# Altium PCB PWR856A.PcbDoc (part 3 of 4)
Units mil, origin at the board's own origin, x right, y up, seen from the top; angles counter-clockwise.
Board outline 4000 x 4000 mil, 8 copper layers (Top Layer, Signal Layer 1, Signal Layer 2, Signal Layer 3, Signal Layer 4, Signal Layer 5, Signal Layer 6, Bottom Layer), stack 60.4 mil thick; 246 components, 78 nets, 563 pads, 817 vias.
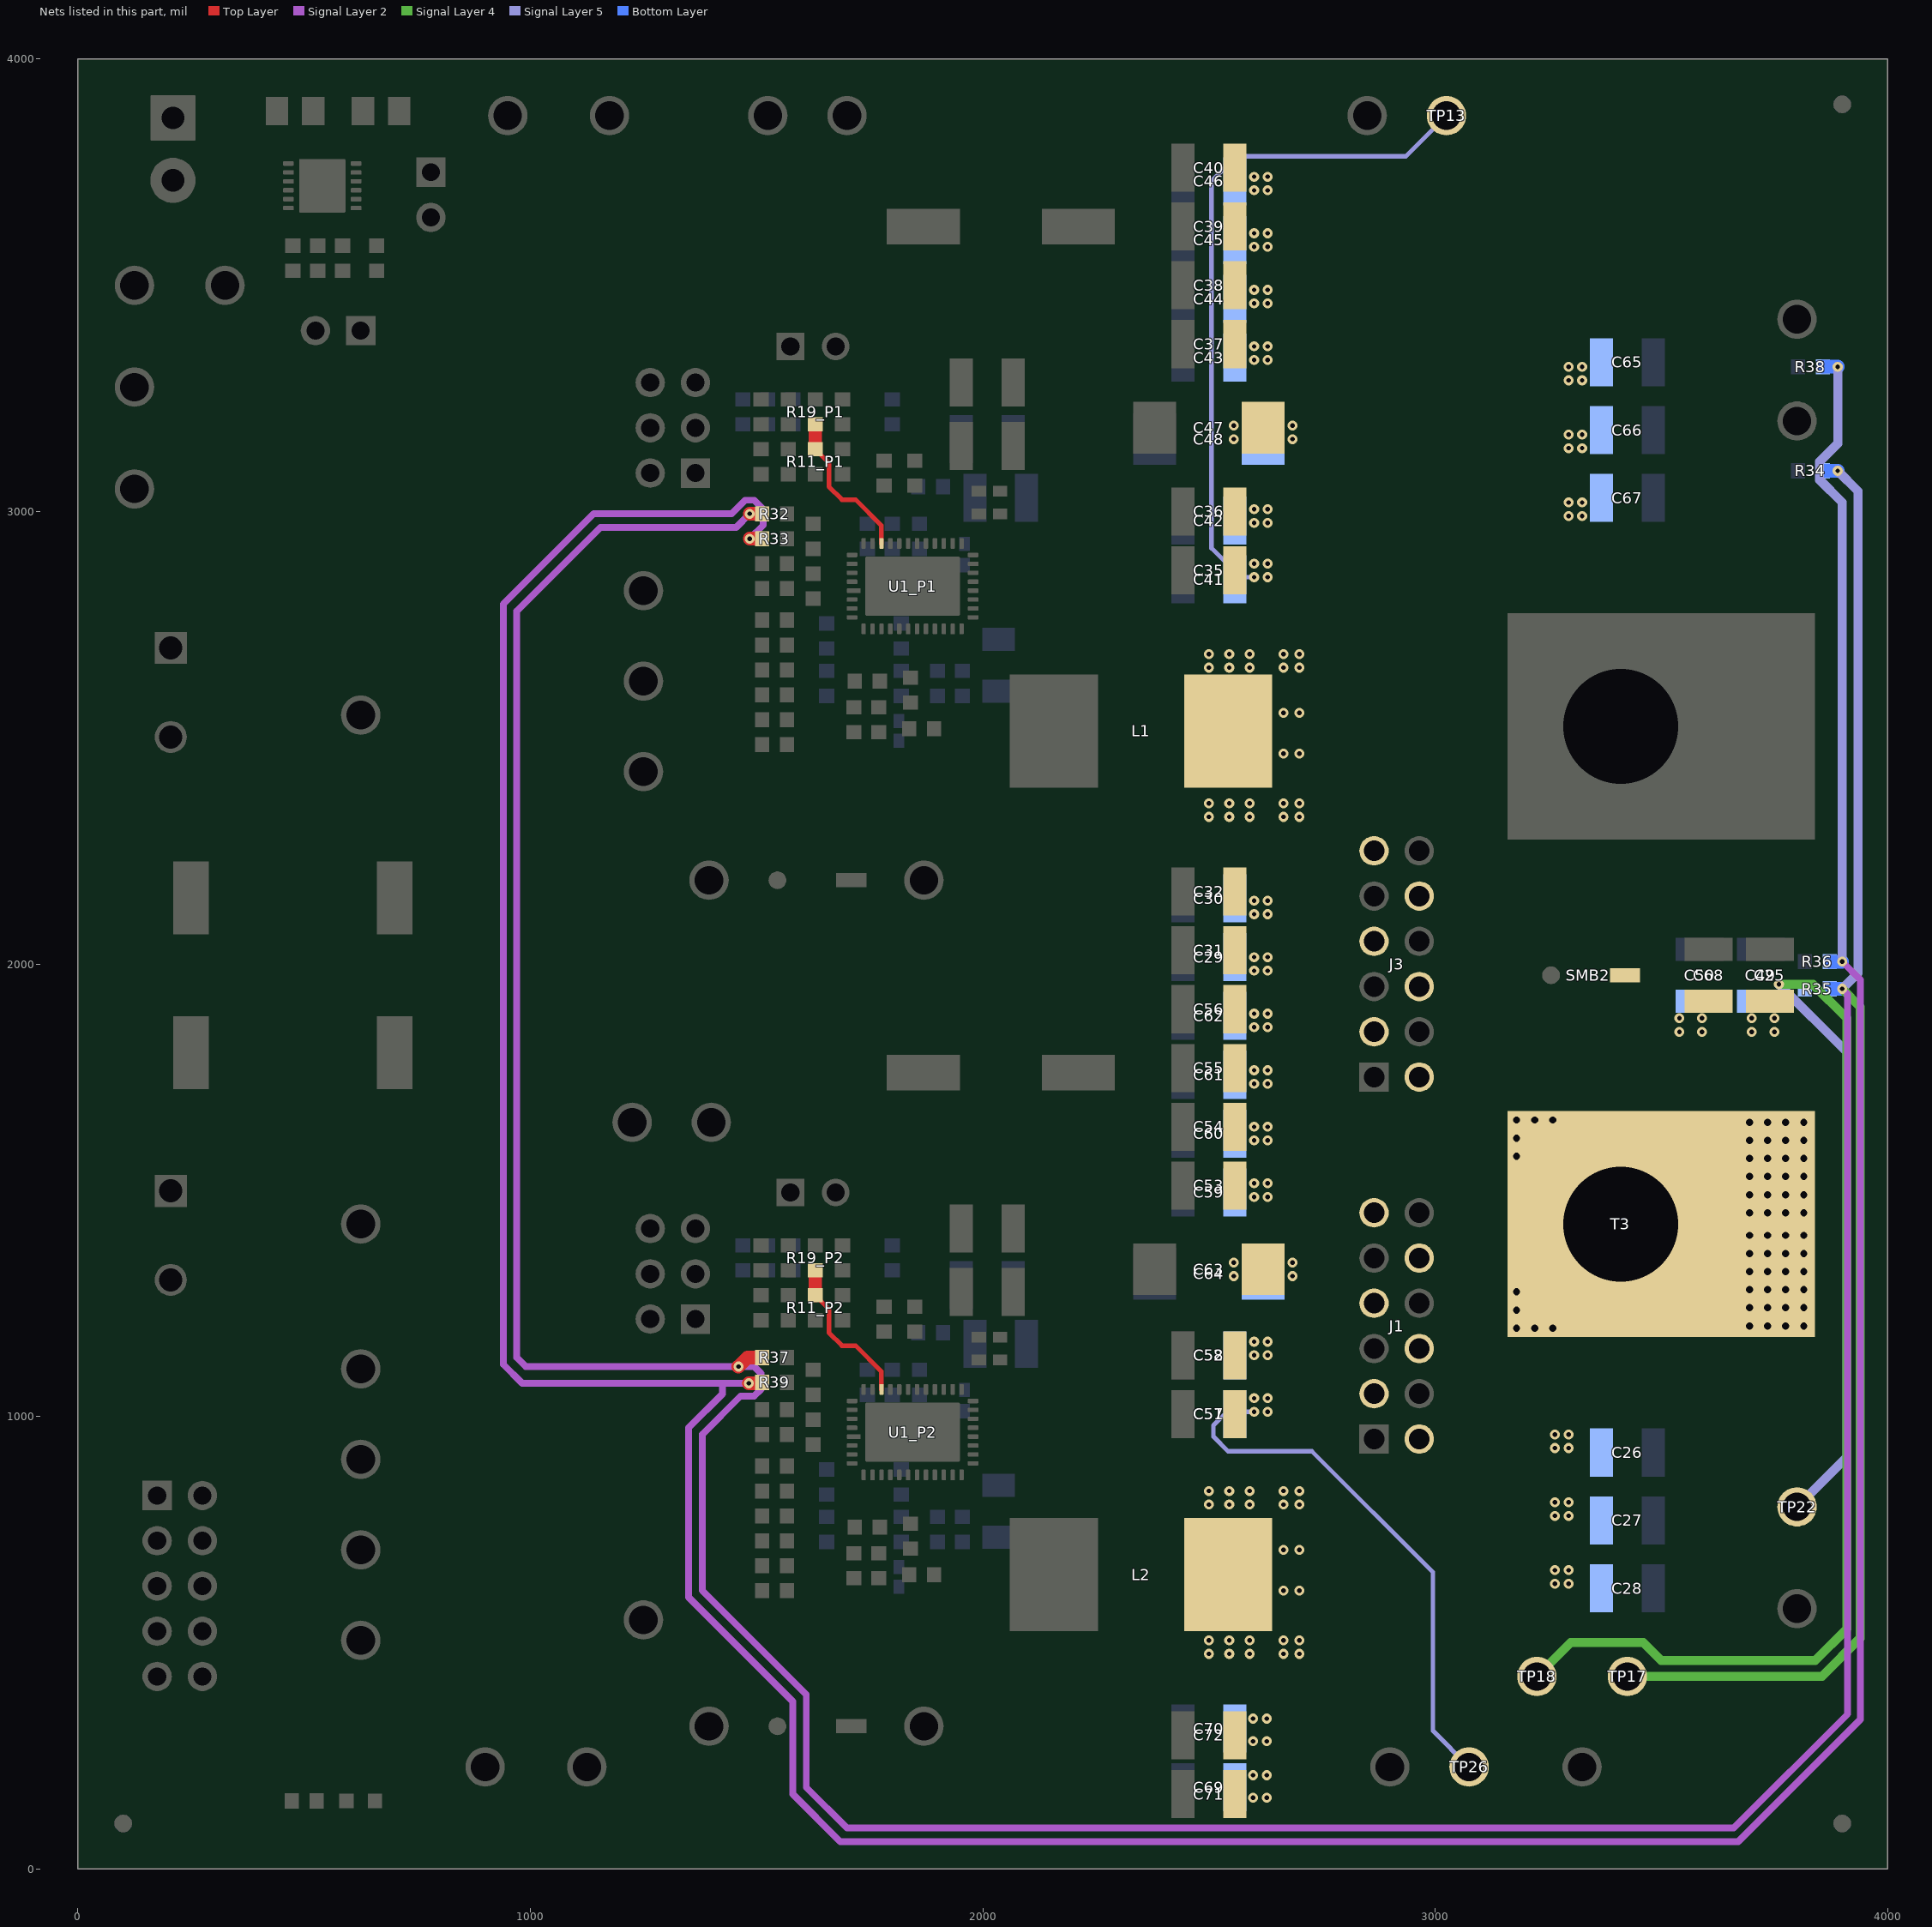
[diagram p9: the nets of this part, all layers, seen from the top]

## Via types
v1: diameter 22, hole 10, Top Layer to Bottom Layer, tented both sides, 676 vias
v2: diameter 32, hole 16, Top Layer to Bottom Layer, 116 vias
v3: diameter 22, hole 10, Top Layer to Bottom Layer, tented bottom, 20 vias
v4: diameter 19.68, hole 7.87, Top Layer to Bottom Layer, 5 vias

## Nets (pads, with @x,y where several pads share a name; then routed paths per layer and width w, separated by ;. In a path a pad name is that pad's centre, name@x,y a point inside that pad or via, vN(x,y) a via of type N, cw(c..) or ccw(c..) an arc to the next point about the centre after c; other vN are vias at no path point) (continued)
VOUT: C25.1 C26.1 C27.1 C28.1 C29.1 C30.1 C31.1 C32.1 C35.2 C36.2 C37.2 C38.2 C39.2 C40.2 C41.2 C42.2 C43.2 C44.2 C45.2 C46.2 C47.1 C48.1 C49.2 C50.2 C51.2 C52.2 C53.2 C54.2 C55.2 C56.2 C57.2 C58.2 C59.2 C60.2 C61.2 C62.2 C63.1 C64.1 C65.1 C66.1 C67.1 C68.1 C69.1 C70.1 C71.1 C72.1 J1.2 J1.3 J1.6 J1.7 J1.10 J1.11 J3.2 J3.3 J3.6 J3.7 J3.10 J3.11 L1.2 L2.2 R35.1 SMB2.1 T3.1 TP13.1 TP18.1 TP22.1 TP26.1 | length 6266.8
  Signal Layer 4 w20: TP18.1@3225,425 3300,500 3460,500 3500,460 3840,460 3910,530 3910,1880 3835,1955 v1(3760,1955)
  Signal Layer 5 w10: v1(2600,1010) 2540,1010 2510,980 2510,955.18 2542.26,922.92 2727.53,922.92 2995,655.46 2995,305 TP26.1@3075,225 ; v1(2600,2855) 2569.61,2855 2505.81,2918.8 2505.81,3730.63 2560.18,3785 2935,3785 TP13.1@3025,3875
  Signal Layer 5 w20: v1(3760,1955) 3910,1805 3910,910 TP22.1@3800,800
  other v1: 2597.81,156.8 2627.81,156.8 2597.81,206.8 2627.81,206.8 2597.81,281.8 2627.81,281.8 2597.81,331.8 2627.81,331.8 2500,475 2545,475 2590,475 2665,475 2700,475 2500,505 2545,505 2590,505 2665,505 2700,505 2665,615 2700,615 3265,630 3295,630 3265,660 3295,660 2665,705 2700,705 3265,780 3295,780 2500,805 2545,805 2590,805 2665,805 2700,805 3265,810 3295,810 2500,835 2545,835 2590,835 2665,835 2700,835 3265,930 3295,930 3265,960 3295,960 2630,1010 2600,1040 2630,1040 2600,1135 2630,1135 2600,1165 2630,1165 2555,1310 2685,1310 2555,1340 2685,1340 2600,1485 2630,1485 2600,1515 2630,1515 2600,1610 2630,1610 2600,1640 2630,1640 2600,1735 2630,1735 2600,1765 2630,1765 3540,1850 3590,1850 3700,1850 3750,1850 2600,1860 2630,1860 3540,1880 3590,1880 3700,1880 3750,1880 2600,1890 2630,1890 2600,1985 2630,1985 2600,2015 2630,2015 2600,2110 2630,2110 2600,2140 2630,2140 2500,2325 2545,2325 2590,2325 2665,2325 2700,2325 2500,2355 2545,2355 2590,2355 2665,2355 2700,2355 2665,2465 2700,2465 2665,2555 2700,2555 2500,2655 2545,2655 2590,2655 2665,2655 2700,2655 2500,2685 2545,2685 2590,2685 2665,2685 2700,2685 2630,2855 2600,2885 2630,2885 2600,2975 2630,2975 3295,2990 3325,2990 2600,3005 2630,3005 3295,3020 3325,3020 3295,3140 3325,3140 2555,3160 2685,3160 3295,3170 3325,3170 2555,3190 2685,3190 3295,3290 3325,3290 3295,3320 3325,3320 2600,3335 2630,3335 2600,3365 2630,3365 2600,3460 2630,3460 2600,3490 2630,3490 2600,3585 2630,3585 2600,3615 2630,3615 2600,3710 2630,3710 2600,3740 2630,3740
  other v2: 3180,1195 3220,1195 3260,1195 3695,1200 3735,1200 3775,1200 3815,1200 3180,1235 3695,1240 3735,1240 3775,1240 3815,1240 3180,1275 3695,1280 3735,1280 3775,1280 3815,1280 3695,1320 3735,1320 3775,1320 3815,1320 3695,1360 3735,1360 3775,1360 3815,1360 3695,1400 3735,1400 3775,1400 3815,1400 3695,1450 3735,1450 3775,1450 3815,1450 3695,1490 3735,1490 3775,1490 3815,1490 3695,1530 3735,1530 3775,1530 3815,1530 3695,1570 3735,1570 3775,1570 3815,1570 3180,1575 3695,1610 3735,1610 3775,1610 3815,1610 3180,1615 3695,1650 3735,1650 3775,1650 3815,1650 3180,1655 3220,1655 3260,1655
VSEL_P1: R11_P1.2 R19_P1.1 U1_P1.30 | length 341
  Top Layer w10: R11_P1.2@1630,3137.56 1660,3107.56 1660,3055 1688.87,3026.13 1718.87,3026.13 1776.1,2968.9 U1_P1.30@1776.1,2929.49
  Top Layer w30: R11_P1.2@1630,3137.56 R19_P1.1@1630,3192.44
VSEL_P2: R11_P2.2 R19_P2.1 U1_P2.30 | length 341
  Top Layer w10: R11_P2.2@1630,1267.56 1660,1237.56 1660,1185 1688.87,1156.13 1718.87,1156.13 1776.1,1098.9 U1_P2.30@1776.1,1059.49
  Top Layer w30: R11_P2.2@1630,1267.56 R19_P2.1@1630,1322.44
VSNS_N: R33.2 R36.2 R38.1 R39.2 | length 9704.4
  Top Layer w30: v1(1482.92,1073) R39.2@1510.36,1073 ; v1(1485,2940) R33.2@1512.44,2940
  Signal Layer 2 w15: v1(1482.92,1073) 1424.5,1073 ; v1(1485,2940) 1515,2970 1515,3005 1495,3025 1475,3025 1445,2995 1140,2995 940,2795 940,1115 982,1073 1424.5,1073 ; v1(3900,2005) 3940,1965 3940,330 3670,60 1685,60 1580,165 1580,370 1350,600 1350,975 1424.5,1049.5 1424.5,1073
  Signal Layer 5 w20: v1(3890,3320) 3890,3150 3850,3110 3850,3070 3900,3020 v1(3900,2005)
  Bottom Layer w30: R38.1@3857.56,3320 v1(3890,3320) ; R36.2@3872.56,2005 v1(3900,2005)
VSNS_P: R32.2 R34.2 R35.2 R37.2 TP17.1 | length 11270.3
  Top Layer w10: R37.2@1510.36,1128 R37.2@1510.84,1128
  Top Layer w30: v1(1460,1110) 1480,1130 R37.2@1512.44,1130 ; v1(1485,2995) R32.2@1512.44,2995
  Signal Layer 2 w15: v1(1485,2995) 1455,2965 1155,2965 970,2780 970,1130 990,1110 v1(1460,1110) 1495,1110 1510,1095 1510,1060 1495,1045 1465,1045 1380,960 1380,615 1610,385 1610,180 1700,90 3660,90 3912,342 3912,1933 v1(3900,1945)
  Signal Layer 4 w20: TP17.1@3425,425 3855,425 3940,510 3940,1905 v1(3900,1945)
  Signal Layer 5 w20: v1(3890,3090) 3935,3045 3935,1980 v1(3900,1945)
  Bottom Layer w30: R34.2@3857.56,3090 v1(3890,3090) ; R35.2@3872.56,1945 v1(3900,1945)
pads on no net: FID1.1 FID2.1 FID3.1 FID4.1 FID5.1 FID6.1 H3.0 H4.0 H5.0 H6.0 J2.1 J2.2 J2.3 J2.4 LBL1.0 SH-JP1.0 SH-JP2.0 SH-JP3.0 SH-JP4.0 U1_P1.41@1769.41,2802.91 U1_P1.41@1769.41,2867.09 U1_P1.41@1819.8,2802.91 U1_P1.41@1819.8,2867.09 U1_P1.41@1870.2,2802.91 U1_P1.41@1870.2,2867.09 U1_P1.41@1920.59,2802.91 U1_P1.41@1920.59,2867.09 U1_P2.41@1769.41,932.91 U1_P2.41@1769.41,997.09 U1_P2.41@1819.8,932.91 U1_P2.41@1819.8,997.09 U1_P2.41@1870.2,932.91 U1_P2.41@1870.2,997.09 U1_P2.41@1920.59,932.91 U1_P2.41@1920.59,997.09

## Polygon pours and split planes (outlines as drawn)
SW_P2 on Bottom Layer "BOTTOM_LAYER_SW_P2_P585" (solid, remove dead copper, pour order 585): 1890,845 ccw(c1890,835) 1880,835 1880,765 ccw(c1890,765) 1890,755 1965,755 ccw(c1965,765) 1975,765 1975,792.93 ccw(c1957.93,792.93) 1970,805 1937.07,837.93 ccw(c1920,820.86) 1920,845
NetC12_P2_2 on Bottom Layer "BOTTOM_LAYER_NETC12_P2_2_P584" (solid, remove dead copper, pour order 584): 1980,740 ccw(c1980,750) 1990,750 1990,760 cw(c2000,760) 2000,770 2070,770 cw(c2070,760) 2080,760 2080,705 cw(c2070,705) 2070,695 1945,695 cw(c1945,705) 1935,705 1935,735 cw(c1940,735) 1940,740
NetC12_P1_2 on Bottom Layer "BOTTOM_LAYER_NETC12_P1_2_P583" (solid, remove dead copper, pour order 583): 1980,2610 ccw(c1980,2620) 1990,2620 1990,2630 cw(c2000,2630) 2000,2640 2070,2640 cw(c2070,2630) 2080,2630 2080,2575 cw(c2070,2575) 2070,2565 1945,2565 cw(c1945,2575) 1935,2575 1935,2605 cw(c1940,2605) 1940,2610
SW_P1 on Bottom Layer "BOTTOM_LAYER_SW_P1_P582" (solid, remove dead copper, pour order 582): 1890,2715 ccw(c1890,2705) 1880,2705 1880,2635 ccw(c1890,2635) 1890,2625 1965,2625 ccw(c1965,2635) 1975,2635 1975,2662.93 ccw(c1957.93,2662.93) 1970,2675 1937.07,2707.93 ccw(c1920,2690.86) 1920,2715
PVIN_P1 on Bottom Layer "BOTTOM_LAYER_PVIN_P1_P581" (solid, remove dead copper, pour order 581): 818.58,1990 cw(c818.58,1890) 889.29,1960.71 1170.71,1679.29 ccw(c1241.42,1750) 1241.42,1650 1465,1650 1465,1605 ccw(c1490,1605) 1490,1580 1691.36,1580 cw(c1691.36,1536.64) 1722.02,1567.3 1830.71,1458.61 cw(c1760,1387.9) 1860,1387.9 1860,1355 2020,1355 2020,1950 ccw(c1970,1950) 1970,2000 1591.42,2000 cw(c1591.42,2100) 1520.71,2029.29 1169.29,2380.71 cw(c1240,2451.42) 1140,2451.42 1140,3248.58 cw(c1240,3248.58) 1169.29,3319.29 1270.71,3420.71 cw(c1341.42,3350) 1341.42,3450 1691.72,3450 cw(c1691.72,3381.72) 1740,3430 1820.71,3349.29 cw(c1750,3278.58) 1850,3278.58 1850,3220 2020,3220 2020,3760 ccw(c1970,3760) 1970,3810 1131.42,3810 ccw(c1131.42,3710) 1060.71,3780.71 769.29,3489.29 cw(c698.58,3560) 698.58,3460 610,3460 ccw(c610,3430) 580,3430 580,3391.42 cw(c480,3391.42) 550.71,3320.71 129.29,2899.29 ccw(c200,2828.58) 100,2828.58 100,2040 ccw(c150,2040) 150,1990
PVIN_P1 on Bottom Layer "BOTTOM_LAYER_PVIN_P1_P580" (solid, remove dead copper, pour order 580): 1967.93,1040 ccw(c1967.93,1057.07) 1980,1045 1991.72,1056.72 ccw(c1923.43,1125) 2020,1125 2020,1630 1845,1630 1845,1440 cw(c1835,1440) 1835,1430 1825,1430 1825,1420 cw(c1788.79,1383.79) 1840,1383.79 1840,1346.21 ccw(c1891.21,1346.21) 1855,1310 1880.86,1284.14 cw(c1846.72,1250) 1895,1250 1895,1060 ccw(c1915,1060) 1915,1040
PVIN_P1 on Bottom Layer "BOTTOM_LAYER_PVIN_P1_P579" (solid, remove dead copper, pour order 579): 1967.93,2910 ccw(c1967.93,2927.07) 1980,2915 1991.72,2926.72 ccw(c1923.43,2995) 2020,2995 2020,3500 1845,3500 1845,3310 cw(c1835,3310) 1835,3300 1825,3300 1825,3290 cw(c1788.79,3253.79) 1840,3253.79 1840,3216.21 ccw(c1891.21,3216.21) 1855,3180 1880.86,3154.14 cw(c1846.72,3120) 1895,3120 1895,2930 ccw(c1915,2930) 1915,2910
AVIN_P2 on Bottom Layer "BOTTOM_LAYER_AVIN_P2_P577" (solid, remove dead copper, pour order 577): 1870,1080 ccw(c1870,1090) 1880,1090 1880,1192.93 ccw(c1862.93,1192.93) 1875,1205 1832.07,1247.93 cw(c1849.14,1265) 1825,1265 1825,1335 ccw(c1815,1335) 1815,1345 1785,1345 ccw(c1785,1340) 1780,1340 1780,1312.07 ccw(c1797.07,1312.07) 1785,1300 1797.93,1287.07 cw(c1780.86,1270) 1805,1270 1805,1209.14 ccw(c1863.28,1209.14) 1822.07,1167.93 1825.86,1164.14 cw(c1791.72,1130) 1840,1130 1840,1090 ccw(c1850,1090) 1850,1080
AVIN_P1 on Bottom Layer "BOTTOM_LAYER_AVIN_P1_P576" (solid, remove dead copper, pour order 576): 1870,2950 ccw(c1870,2960) 1880,2960 1880,3062.93 ccw(c1862.93,3062.93) 1875,3075 1832.07,3117.93 cw(c1849.14,3135) 1825,3135 1825,3205 ccw(c1815,3205) 1815,3215 1785,3215 ccw(c1785,3210) 1780,3210 1780,3182.07 ccw(c1797.07,3182.07) 1785,3170 1797.93,3157.07 cw(c1780.86,3140) 1805,3140 1805,3079.14 ccw(c1863.28,3079.14) 1822.07,3037.93 1825.86,3034.14 cw(c1791.72,3000) 1840,3000 1840,2960 ccw(c1850,2960) 1850,2950
VOUT on Bottom Layer "BOTTOM_LAYER_VOUT_P563" (solid, remove dead copper, pour order 563): 2540,3820 ccw(c2540,3770) 2490,3770 2490,150 ccw(c2540,150) 2540,100 2758.58,100 ccw(c2758.58,200) 2829.29,129.29 3170.71,470.71 cw(c3241.42,400) 3241.42,500 3370,500 ccw(c3370,550) 3420,550 3420,1000 cw(c3470,1000) 3470,1050 3860,1050 ccw(c3860,1100) 3910,1100 3910,1890 ccw(c3890,1890) 3890,1910 3850,1910 cw(c3850,1920) 3840,1920 3840,1960 ccw(c3830,1960) 3830,1970 3341.42,1970 cw(c3341.42,2070) 3270.71,1999.29 3159.29,2110.71 cw(c3230,2181.42) 3130,2181.42 3130,2830 cw(c3180,2830) 3180,2880 3370,2880 ccw(c3370,2930) 3420,2930 3420,3488.58 ccw(c3320,3488.58) 3390.71,3559.29 3159.29,3790.71 ccw(c3088.58,3720) 3088.58,3820
GND_P1 on Bottom Layer "BOTTOM_LAYER_GND_P1_P560" (solid, remove dead copper, pour order 560): 0,4000 4000,4000 4000,0 4000,4000 0,4000
GND_P1 on Bottom Layer "BOTTOM_LAYER_GND_P1_P606" (solid, remove dead copper, pour order 606): 1740,1070 1875,1070 cw(c1875,1060) 1885,1060 1885,1040 ccw(c1895,1040) 1895,1030 1965.86,1030 ccw(c1965.86,1064.14) 1990,1040 2001.72,1051.72 ccw(c1933.43,1120) 2030,1120 2030,1940 2480,1940 2480,150 ccw(c2540,150) 2540,90 2660,90 2660,25 1935,25 1935,665 cw(c1955,665) 1955,685 2070,685 ccw(c2070,705) 2090,705 2090,760 ccw(c2070,760) 2070,780 2051.42,780 cw(c2051.42,880) 1980.71,809.29 1940,850 ccw(c1915.86,825.86) 1915.86,860 1739.14,860 cw(c1739.14,894.14) 1715,870 1702.68,882.32 cw(c1745.36,925) 1685,925 1685,1010.86 cw(c1719.14,1010.86) 1695,1035 1722.93,1062.93 cw(c1740,1045.86)
GND_P1 on Bottom Layer "BOTTOM_LAYER_GND_P1_P607" (solid, remove dead copper, pour order 607): 150,1980 cw(c150,2040) 90,2040 90,2155 25,2155 25,100 ccw(c100,100) 100,25 2020,25 2020,335 1935,335 1935,315 cw(c1870,315) 1870,250 cw(c1870,315) 1805,315 1805,320 cw(c1865.36,320) 1822.68,362.68 1840,380 ccw(c1791.72,428.28) 1860,428.28 1860,555 ccw(c1830,555) 1830,585 1795,585 cw(c1795,610) 1770,610 1770,705 ccw(c1740,705) 1740,735 1680,735 ccw(c1660,735) 1660,755 1585,755 cw(c1585,780) 1560,780 1560,974.64 cw(c1645.36,974.64) 1585,1035 1645.71,1095.71 ccw(c1575,1166.42) 1675,1166.42 1675,1425 ccw(c1655,1425) 1655,1445 1630,1445 ccw(c1630,1425) 1610,1425 1610,1300 cw(c1600,1300) 1600,1290 1365,1290 1365,1335 1555,1335 1555,1362.36 ccw(c1495.69,1362.36) 1537.63,1404.3 1501.31,1440.62 cw(c1540.7,1480) 1485,1480 1485,1508.4 ccw(c1385,1508.4) 1455.71,1579.11 1424.11,1610.71 ccw(c1353.4,1540) 1353.4,1640 1236.42,1640 cw(c1236.42,1740) 1165.71,1669.29 884.29,1950.71 ccw(c813.58,1880) 813.58,1980
GND_P1 on Bottom Layer "BOTTOM_LAYER_GND_P1_P608" (solid, remove dead copper, pour order 608): 1150,3243.58 cw(c1250,3243.58) 1179.29,3314.29 1275.71,3410.71 cw(c1346.42,3340) 1346.42,3440 1460,3440 cw(c1460,3420) 1480,3420 1480,3339.14 ccw(c1502.07,3339.14) 1486.46,3323.54 1540,3270 cw(c1515.86,3245.86) 1550,3245.86 1550,3175 ccw(c1555,3175) 1555,3170 1600,3170 ccw(c1600,3180) 1610,3180 1610,3290 cw(c1620,3290) 1620,3300 1670,3300 cw(c1670,3290) 1680,3290 1680,3135 ccw(c1728.28,3135) 1694.14,3100.86 1705,3090 cw(c1680.86,3065.86) 1715,3065.86 1715,3055 cw(c1654.64,3055) 1697.32,3012.32 1579.14,2894.14 ccw(c1613.28,2860) 1565,2860 1565,2667.28 ccw(c1569.55,2667.28) 1566.33,2664.06 1566.33,2643.67 ccw(c1585,2643.67) 1585,2625 1697.93,2625 cw(c1697.93,2607.93) 1710,2620 1714.39,2615.61 ccw(c1740,2641.21) 1740,2605 1765,2605 cw(c1765,2590) 1780,2590 1780,2470 ccw(c1795,2470) 1795,2455 1845,2455 cw(c1845,2440) 1860,2440 1860,2281.21 cw(c1820.86,2281.21) 1848.54,2253.54 1826.21,2231.21 ccw(c1877.43,2180) 1805,2180 ccw(c1865,2180) 1865,2120 1870,2120 ccw(c1870,2185) 1935,2185 1935,2525 cw(c1960,2525) 1960,2550 2080,2550 ccw(c2080,2565) 2095,2565 2095,2640 ccw(c2080,2640) 2080,2655 2056.42,2655 cw(c2056.42,2755) 1985.71,2684.29 1949.14,2720.86 ccw(c1915,2686.72) 1915,2735 1732.07,2735 cw(c1732.07,2752.07) 1720,2740 1690.61,2769.39 cw(c1716.21,2795) 1680,2795 1680,2880.86 cw(c1714.14,2880.86) 1690,2905 1709.39,2924.39 cw(c1735,2898.79) 1735,2935 1875,2935 cw(c1875,2930) 1880,2930 1880,2910 ccw(c1890,2910) 1890,2900 1965.86,2900 ccw(c1965.86,2934.14) 1990,2910 2001.72,2921.72 ccw(c1933.43,2990) 2030,2990 2030,3760 ccw(c1970,3760) 1970,3820 1890,3820 1890,3975 2740,3975 2740,3830 2540,3830 ccw(c2540,3770) 2480,3770 2480,1810 2030,1810 2030,1950 ccw(c1970,1950) 1970,2010 1596.42,2010 cw(c1596.42,2110) 1525.71,2039.29 1179.29,2385.71 cw(c1250,2456.42) 1150,2456.42
GND_P1 on Bottom Layer "BOTTOM_LAYER_GND_P1_P609" (solid, remove dead copper, pour order 609): 2635,25 3900,25 ccw(c3900,100) 3975,100 3975,3900 ccw(c3900,3900) 3900,3975 2640,3975 2640,3830 3098.58,3830 cw(c3098.58,3730) 3169.29,3800.71 3412.32,3557.68 cw(c3369.64,3515) 3430,3515 3430,2925 cw(c3375,2925) 3375,2870 3185,2870 ccw(c3185,2825) 3140,2825 3140,2186.42 ccw(c3240,2186.42) 3169.29,2115.71 3275.71,2009.29 ccw(c3346.42,2080) 3346.42,1980 3830,1980 ccw(c3830,1990) 3840,1990 3840,2025 cw(c3850,2025) 3850,2035 3895,2035 cw(c3895,2010) 3920,2010 3920,1090 cw(c3870,1090) 3870,1040 3475,1040 ccw(c3475,995) 3430,995 3430,545 cw(c3375,545) 3375,490 3251.42,490 ccw(c3251.42,390) 3180.71,460.71 2839.29,119.29 cw(c2768.58,190) 2768.58,90 2635,90
GND_P1 on Bottom Layer "BOTTOM_LAYER_GND_P1_P610" (solid, remove dead copper, pour order 610): 90,2125 90,2833.58 cw(c190,2833.58) 119.29,2904.29 540.71,3325.71 ccw(c470,3396.42) 570,3396.42 570,3425 cw(c615,3425) 615,3470 688.58,3470 ccw(c688.58,3570) 759.29,3499.29 1050.71,3790.71 cw(c1121.42,3720) 1121.42,3820 1960,3820 1960,3975 75,3975 ccw(c75,3925) 25,3925 25,2125
VDD5_P2 on Bottom Layer "BOTTOM_LAYER_VDD5_P2_P605" (solid, remove dead copper, pour order 605): 1575,981.72 cw(c1631.21,981.72) 1591.46,1021.46 1710.17,1140.17 ccw(c1670.35,1180) 1726.67,1180 1726.67,1203.9 ccw(c1703.9,1203.9) 1720,1220 1703.74,1236.26 cw(c1733.83,1266.35) 1691.28,1266.35 1691.28,1425.7 ccw(c1635.7,1425.7) 1675,1465 1675,1510 1695,1510 1723.79,1481.21 cw(c1672.57,1430) 1745,1430 1745,1276.79 ccw(c1784.69,1276.79) 1756.62,1248.72 1782.68,1222.67 cw(c1765.02,1205) 1790,1205 1790,1203.28 ccw(c1858.28,1203.28) 1810,1155 cw(c1785.86,1130.86) 1820,1130.86 1820,1085 cw(c1815,1085) 1815,1080 1734.14,1080 ccw(c1734.14,1045.86) 1710,1070 1646.21,1006.21 ccw(c1697.43,955) 1625,955 1625,860 ccw(c1635,860) 1635,850 1670,850 cw(c1670,840) 1680,840 1680,835 ccw(c1690,835) 1690,825 1720,825 ccw(c1720,835) 1730,835 1730,840 cw(c1740,840) 1740,850 1835,850 cw(c1835,840) 1845,840 1845,765 cw(c1835,765) 1835,755 1585,755 cw(c1585,765) 1575,765
VDD5_P1 on Bottom Layer "BOTTOM_LAYER_VDD5_P1_P604" (solid, remove dead copper, pour order 604): 1575,2851.72 cw(c1631.21,2851.72) 1591.46,2891.46 1710.17,3010.17 ccw(c1670.35,3050) 1726.67,3050 1726.67,3073.9 ccw(c1703.9,3073.9) 1720,3090 1703.74,3106.26 cw(c1733.83,3136.35) 1691.28,3136.35 1691.28,3295.7 ccw(c1635.7,3295.7) 1675,3335 1675,3380 1695,3380 1723.79,3351.21 cw(c1672.57,3300) 1745,3300 1745,3146.79 ccw(c1784.69,3146.79) 1756.62,3118.72 1782.68,3092.67 cw(c1765.02,3075) 1790,3075 1790,3073.28 ccw(c1858.28,3073.28) 1810,3025 cw(c1785.86,3000.86) 1820,3000.86 1820,2955 cw(c1815,2955) 1815,2950 1734.14,2950 ccw(c1734.14,2915.86) 1710,2940 1646.21,2876.21 ccw(c1697.43,2825) 1625,2825 1625,2730 ccw(c1635,2730) 1635,2720 1670,2720 cw(c1670,2710) 1680,2710 1680,2705 ccw(c1690,2705) 1690,2695 1720,2695 ccw(c1720,2705) 1730,2705 1730,2710 cw(c1740,2710) 1740,2720 1835,2720 cw(c1835,2710) 1845,2710 1845,2635 cw(c1835,2635) 1835,2625 1585,2625 cw(c1585,2635) 1575,2635
VDD5_P2 on Top Layer "TOP_LAYER_VDD5_P2_P578" (solid, remove dead copper, pour order 578): 1735,1228 1755,1228 1755,1221 ccw(c1770,1221) 1770,1206 1796,1206 cw(c1796,1201) 1801,1201 1801,1148.07 ccw(c1818.07,1148.07) 1806,1136 1815.76,1126.24 cw(c1805.52,1116) 1820,1116 1820,1050 1811,1050 1811,1111.76 ccw(c1800.76,1111.76) 1808,1119 1747.02,1179.98 cw(c1776.04,1209) 1735,1209
VDD5_P1 on Top Layer "TOP_LAYER_VDD5_P1_P575" (solid, remove dead copper, pour order 575): 1735,3098 1755,3098 1755,3091 ccw(c1770,3091) 1770,3076 1796,3076 cw(c1796,3071) 1801,3071 1801,3018.07 ccw(c1818.07,3018.07) 1806,3006 1815.76,2996.24 cw(c1805.52,2986) 1820,2986 1820,2920 1811,2920 1811,2981.76 ccw(c1800.76,2981.76) 1808,2989 1747.02,3049.98 cw(c1776.04,3079) 1735,3079
NetC17_P2_2 on Top Layer "TOP_LAYER_NETC17_P2_2_P574" (solid, remove dead copper, pour order 574): 1545,1000 ccw(c1555,1000) 1555,990 1585,990 ccw(c1585,995) 1590,995 1590,1015 cw(c1600,1015) 1600,1025 1640,1025 ccw(c1640,1030) 1645,1030 1645,1060 ccw(c1640,1060) 1640,1065 1600,1065 cw(c1600,1075) 1590,1075 1590,1085 ccw(c1585,1085) 1585,1090 1550,1090 ccw(c1550,1085) 1545,1085
PG_P2 on Top Layer "TOP_LAYER_PG_P2_P573" (solid, remove dead copper, pour order 573): 1705.51,830 ccw(c1705.51,850.49) 1720,836 1736.76,852.76 ccw(c1726.51,863) 1741,863 1741,880 1732,880 1732,869 cw(c1727,869) 1727,864 1706.07,864 ccw(c1706.07,846.93) 1694,859 1673.41,838.41 ccw(c1676.83,835) 1672,835 1672,825 1673,825 cw(c1685.07,812.93) 1685.07,830
PG_P1 on Top Layer "TOP_LAYER_PG_P1_P572" (solid, remove dead copper, pour order 572): 1705.51,2700 ccw(c1705.51,2720.49) 1720,2706 1736.76,2722.76 ccw(c1726.51,2733) 1741,2733 1741,2750 1732,2750 1732,2739 cw(c1727,2739) 1727,2734 1706.07,2734 ccw(c1706.07,2716.93) 1694,2729 1673.41,2708.41 ccw(c1676.83,2705) 1672,2705 1672,2695 1673,2695 cw(c1685.07,2682.93) 1685.07,2700
NetC17_P1_2 on Top Layer "TOP_LAYER_NETC17_P1_2_P571" (solid, remove dead copper, pour order 571): 1545,2870 ccw(c1555,2870) 1555,2860 1585,2860 ccw(c1585,2865) 1590,2865 1590,2885 cw(c1600,2885) 1600,2895 1640,2895 ccw(c1640,2900) 1645,2900 1645,2930 ccw(c1640,2930) 1640,2935 1600,2935 cw(c1600,2945) 1590,2945 1590,2955 ccw(c1585,2955) 1585,2960 1550,2960 ccw(c1550,2955) 1545,2955
PVIN_P1 on Top Layer "TOP_LAYER_PVIN_P1_P570" (solid, remove dead copper, pour order 570): 798.58,1990 cw(c798.58,1890) 869.29,1960.71 1185,1645 1455,1645 1480.71,1619.29 ccw(c1551.42,1690) 1551.42,1590 1668.58,1590 cw(c1668.58,1490) 1739.29,1560.71 1855.71,1444.29 cw(c1785,1373.58) 1885,1373.58 1885,1325 2010,1325 2010,1925 ccw(c1985,1925) 1985,1950 1581.42,1950 cw(c1581.42,2050) 1510.71,1979.29 1159.29,2330.71 cw(c1230,2401.42) 1130,2401.42 1130,3228.58 cw(c1230,3228.58) 1159.29,3299.29 1280.71,3420.71 cw(c1351.42,3350) 1351.42,3450 1678.58,3450 cw(c1678.58,3350) 1749.29,3420.71 1855.71,3314.29 cw(c1785,3243.58) 1885,3243.58 1885,3175 2010,3175 2010,3760 ccw(c1960,3760) 1960,3810 1151.42,3810 ccw(c1151.42,3710) 1080.71,3780.71 784.29,3484.29 cw(c713.58,3555) 713.58,3455 590,3455 ccw(c590,3440) 575,3440 575,3366.42 cw(c475,3366.42) 545.71,3295.71 129.29,2879.29 ccw(c200,2808.58) 100,2808.58 100,2040 ccw(c150,2040) 150,1990
PVIN_P1 on Top Layer "TOP_LAYER_PVIN_P1_P569" (solid, remove dead copper, pour order 569): 1945.86,1045 ccw(c1945.86,1079.14) 1970,1055 1992.32,1077.32 ccw(c1949.64,1120) 2010,1120 2010,1500 1885,1500 1885,1142.07 cw(c1867.93,1142.07) 1880,1130 1873.54,1123.54 ccw(c1882.07,1115) 1870,1115 1870,1050 ccw(c1875,1050) 1875,1045
PVIN_P1 on Top Layer "TOP_LAYER_PVIN_P1_P568" (solid, remove dead copper, pour order 568): 1945.86,2915 ccw(c1945.86,2949.14) 1970,2925 1992.32,2947.32 ccw(c1949.64,2990) 2010,2990 2010,3370 1885,3370 1885,3012.07 cw(c1867.93,3012.07) 1880,3000 1873.54,2993.54 ccw(c1882.07,2985) 1870,2985 1870,2920 ccw(c1875,2920) 1875,2915
GND_P1 on Top Layer "TOP_LAYER_GND_P1_P567" (solid, remove dead copper, pour order 567): 1949.93,900 cw(c1949.93,882.93) 1962,895 1963.46,893.54 ccw(c1972,902.07) 1972,890 2430,890 ccw(c2430,940) 2480,940 2480,1950 2020,1950 2020,1118.28 cw(c1951.72,1118.28) 2000,1070 1977.68,1047.68 cw(c1935,1090.36) 1935,1030 1740,1030 1740,900
GND_P1 on Top Layer "TOP_LAYER_GND_P1_P566" (solid, remove dead copper, pour order 566): 1949.93,2770 cw(c1949.93,2752.93) 1962,2765 1963.46,2763.54 ccw(c1972,2772.07) 1972,2760 2430,2760 ccw(c2430,2810) 2480,2810 2480,3820 2020,3820 2020,2988.28 cw(c1951.72,2988.28) 2000,2940 1977.68,2917.68 cw(c1935,2960.36) 1935,2900 1740,2900 1740,2770
SW_P2 on Top Layer "TOP_LAYER_SW_P2_P565" (solid, remove dead copper, pour order 565): 2299.52,432 ccw(c2299.52,482) 2349.52,482 2349.52,822 ccw(c2299.52,822) 2299.52,872 1976.59,872 cw(c1976.59,889.07) 1964.52,877 1958.06,883.46 ccw(c1949.52,874.93) 1949.52,887 1874.52,887 ccw(c1874.52,882) 1869.52,882 1869.52,587.36 ccw(c1954.88,587.36) 1894.52,527 1960.23,461.29 ccw(c2030.94,532) 2030.94,432
SW_P1 on Top Layer "TOP_LAYER_SW_P1_P564" (solid, remove dead copper, pour order 564): 2300,2300 ccw(c2300,2350) 2350,2350 2350,2690 ccw(c2300,2690) 2300,2740 1977.07,2740 cw(c1977.07,2757.07) 1965,2745 1958.54,2751.46 ccw(c1950,2742.93) 1950,2755 1875,2755 ccw(c1875,2750) 1870,2750 1870,2455.36 ccw(c1955.36,2455.36) 1895,2395 1960.71,2329.29 ccw(c2031.42,2400) 2031.42,2300
AGND_P2 on Top Layer "TOP_LAYER_AGND_P2_P561" (solid, remove dead copper, pour order 561): 1702.92,1408 cw(c1702.92,1398) 1712.92,1398 1712.92,1368 cw(c1702.92,1368) 1702.92,1358 1492.92,1358 cw(c1492.92,1368) 1482.92,1368 1482.92,1398 cw(c1492.92,1398) 1492.92,1408
AGND_P1 on Top Layer "TOP_LAYER_AGND_P1_P562" (solid, remove dead copper, pour order 562): 1710,3270 cw(c1710,3260) 1720,3260 1720,3235 cw(c1710,3235) 1710,3225 1485,3225 cw(c1485,3235) 1475,3235 1475,3260 cw(c1485,3260) 1485,3270
GND_P1 on Top Layer "TOP_LAYER_GND_P1_P595" (solid, remove dead copper, pour order 595): 595,3565 ccw(c595,3575) 605,3575 605,3617.93 cw(c622.07,3617.93) 610,3630 626.46,3646.46 ccw(c617.93,3655) 630,3655 630,3671 ccw(c625,3671) 625,3676 598,3676 cw(c598,3681) 593,3681 593,3776 cw(c609.9,3776) 597.95,3787.95 659.39,3849.39 ccw(c633.79,3875) 670,3875 670,3940 ccw(c640,3940) 640,3970 510,3970 ccw(c510,3947) 487,3947 487,3682 cw(c481,3682) 481,3676 452.24,3676 ccw(c452.24,3665.76) 445,3673 425.66,3653.66 ccw(c439.31,3640) 420,3640 420,3581 ccw(c436,3581) 436,3565
GND_P1 on Top Layer "TOP_LAYER_GND_P1_P596" (solid, remove dead copper, pour order 596): 2440,415 cw(c2442.5,377.5) 2480,380 2480,145 ccw(c2535,145) 2535,90 2755,90 2755,25 87.08,25 cw(c87.08,86.59) 25.49,86.59 25.49,1980 793.58,1980 cw(c793.58,1880) 864.29,1950.71 1177.93,1637.07 ccw(c1195,1654.14) 1195,1630 1455,1630 1455,605 ccw(c1505,605) 1505,555 1793.58,555 cw(c1793.58,455) 1864.29,525.71 1940.71,449.29 ccw(c2016.75,515.78) 2010,415
GND_P1 on Top Layer "TOP_LAYER_GND_P1_P597" (solid, remove dead copper, pour order 597): 2020,1735 2020,1935 ccw(c1995,1935) 1995,1960 1591.42,1960 cw(c1591.42,2060) 1520.71,1989.29 1169.29,2340.71 cw(c1240,2411.42) 1140,2411.42 1140,3218.58 cw(c1240,3218.58) 1169.29,3289.29 1290.71,3410.71 cw(c1361.42,3340) 1361.42,3440 1440,3440 cw(c1440,3425) 1455,3425 1455,2470 ccw(c1490,2470) 1490,2435 1778.58,2435 cw(c1778.58,2335) 1849.29,2405.71 1950,2305 ccw(c2010.36,2365.36) 2010.36,2280 2415.86,2280 cw(c2415.86,2245.86) 2440,2270 2451.72,2258.28 cw(c2383.43,2190) 2480,2190 2480,1735
VOUT on Top Layer "TOP_LAYER_VOUT_P598" (solid, remove dead copper, pour order 598): 2758.58,100 ccw(c2758.58,200) 2829.29,129.29 3170.71,470.71 cw(c3241.42,400) 3241.42,500 3370,500 ccw(c3370,550) 3420,550 3420,1000 cw(c3470,1000) 3470,1050 3860,1050 ccw(c3860,1100) 3910,1100 3910,1870 ccw(c3810,1870) 3810,1970 3549.14,1970 cw(c3549.14,2004.14) 3525,1980 ccw(c3488.79,1943.79) 3488.79,1995 3385,1995 ccw(c3385,1985) 3375,1985 3375,1965 ccw(c3385,1965) 3385,1955 3465,1955 cw(c3465,1940) 3480,1940 3480,1930 cw(c3380,1930) 3380,1830 3185,1830 cw(c3185,1885) 3130,1885 3130,2830 cw(c3180,2830) 3180,2880 3370,2880 ccw(c3370,2930) 3420,2930 3420,3488.58 ccw(c3320,3488.58) 3390.71,3559.29 3159.29,3790.71 ccw(c3088.58,3720) 3088.58,3820 2540,3820 ccw(c2540,3770) 2490,3770 2490,2805 cw(c2435,2805) 2435,2750 ccw(c2435,2710) 2395,2710 2395,2376.42 ccw(c2495,2376.42) 2424.29,2305.71 2468.79,2261.21 cw(c2417.57,2210) 2490,2210 2490,935 cw(c2435,935) 2435,880 ccw(c2435,840) 2395,840 2395,541.42 ccw(c2495,541.42) 2424.29,470.71 2475.86,419.14 cw(c2441.72,385) 2490,385 2490,150 ccw(c2540,150) 2540,100
GND_P1 on Top Layer "TOP_LAYER_GND_P1_P599" (solid, remove dead copper, pour order 599): 2735,25 3910,25 ccw(c3910,90) 3975,90 3975,3905 ccw(c3905,3905) 3905,3975 1890,3975 1890,3820 1965,3820 cw(c1965,3765) 2020,3765 2020,3740 2480,3740 2480,3780 cw(c2530,3780) 2530,3830 3093.58,3830 cw(c3093.58,3730) 3164.29,3800.71 3400.71,3564.29 cw(c3330,3493.58) 3430,3493.58 3430,2930 cw(c3370,2930) 3370,2870 3180,2870 ccw(c3180,2830) 3140,2830 3140,1890 ccw(c3190,1890) 3190,1840 3375,1840 ccw(c3375,1935) 3470,1935 ccw(c3465,1935) 3465,1940 3365,1940 cw(c3365,1955) 3350,1955 3350,1995 cw(c3365,1995) 3365,2010 3488.79,2010 cw(c3488.79,1958.79) 3525,1995 ccw(c3561.21,2031.21) 3561.21,1980 3820,1980 cw(c3820,1880) 3920,1880 3920,1095 cw(c3865,1095) 3865,1040 3475,1040 ccw(c3475,995) 3430,995 3430,550 cw(c3370,550) 3370,490 3251.42,490 ccw(c3251.42,390) 3180.71,460.71 2839.29,119.29 cw(c2768.58,190) 2768.58,90 2735,90
GND_P1 on Top Layer "TOP_LAYER_GND_P1_P600" (solid, remove dead copper, pour order 600): 25,1865 25,3775 cw(c50,3775) 50,3800 250,3800 cw(c250,3780) 270,3780 270,3501.42 ccw(c370,3501.42) 299.29,3430.71 350.71,3379.29 ccw(c421.42,3450) 421.42,3350 525,3350 cw(c525,3335) 540,3335 cw(c479.64,3335) 522.32,3292.32 119.29,2889.29 ccw(c190,2818.58) 90,2818.58 90,2040 ccw(c150,2040) 150,1980 220,1980 220,1865
AVIN on Top Layer "TOP_LAYER_AVIN_P601" (solid, remove dead copper, pour order 601): 55,3970 ccw(c55,3940) 25,3940 25,3840 ccw(c55,3840) 55,3810 260,3810 cw(c260,3790) 280,3790 280,3511.42 ccw(c380,3511.42) 309.29,3440.71 360.71,3389.29 ccw(c431.42,3460) 431.42,3360 545,3360 ccw(c545,3375) 560,3375 560,3470 ccw(c530,3470) 530,3500 442.1,3500 cw(c442.1,3556.62) 385.48,3556.62 385.48,3705.48 cw(c405,3705.48) 405,3725 475,3725 475,3945 ccw(c450,3945) 450,3970
AUX_5V on Top Layer "TOP_LAYER_AUX_5V_P602" (solid, remove dead copper, pour order 602): 715,3725 ccw(c715,3740) 730,3740 730,3795 cw(c740,3795) 740,3805 935,3805 ccw(c935,3875) 1005,3875 1005,3945 ccw(c980,3945) 980,3970 707.05,3970 ccw(c707.05,3942.95) 680,3942.95 680,3866.87 cw(c651.93,3866.87) 671.78,3847.03 608.71,3783.96 ccw(c617.67,3775) 605,3775 605,3725
GND_P1 on Top Layer "TOP_LAYER_GND_P1_P603" (solid, remove dead copper, pour order 603): 1910,3975 1050,3975 ccw(c1050,3945) 1020,3945 1020,3870 cw(c940,3870) 940,3790 845,3790 ccw(c845,3770) 825,3770 825,3715 cw(c815,3715) 815,3705 705,3705 ccw(c705,3685) 685,3685 685,3485 ccw(c700,3485) 700,3470 708.58,3470 ccw(c708.58,3570) 779.29,3499.29 1070.71,3790.71 cw(c1141.42,3720) 1141.42,3820 1910,3820
BP1V5_P1 on Top Layer "TOP_LAYER_BP1V5_P1_P617" (solid, remove dead copper, pour order 617): 1735,2550 ccw(c1735,2555) 1740,2555 1740,2636.1 cw(c1763.9,2636.1) 1747,2653 1758,2664 1758,2677 1735.95,2654.95 cw(c1724,2666.9) 1724,2650 1707,2650 ccw(c1707,2638) 1695,2638 1695,2555 ccw(c1700,2555) 1700,2550
BP1V5_P2 on Top Layer "TOP_LAYER_BP1V5_P2_P618" (solid, remove dead copper, pour order 618): 1735,680 ccw(c1735,685) 1740,685 1740,766.1 cw(c1763.9,766.1) 1747,783 1758,794 1758,807 1735.95,784.95 cw(c1724,796.9) 1724,780 1707,780 ccw(c1707,768) 1695,768 1695,685 ccw(c1700,685) 1700,680
GND_P1 on Signal Layer 5 "SIGNAL_LAYER_5_GND_P1_P616" (solid, remove dead copper, pour order 616): 0,4000 0,0 4000,0 4000,4000
EXT_SYNC on Signal Layer 5 "SIGNAL_LAYER_5_EXT_SYNC_P612" (solid, remove dead copper, pour order 612): 1080,1920.5 1080,1715.5 1060,1715.5 1060,1736.36 ccw(c1025.86,1736.36) 1050,1760.5 1045,1765.5 ccw(c1020.86,1741.36) 1020.86,1775.5 1020,1775.5 ccw(c1020,1751.36) 1002.93,1768.43 950,1715.5 935,1730.5 1049.39,1844.89 ccw(c1023.79,1870.5) 1060,1870.5 1060,1920.5
PVIN_P1 on Signal Layer 5 "SIGNAL_LAYER_5_PVIN_P1_P586" (solid, remove dead copper, pour order 586): 1985,2930 ccw(c1985,2940) 1995,2940 1995,2950.86 cw(c2029.14,2950.86) 2005,2975 2005,2985 cw(c2005,2995) 1995,2995 2012.93,3012.93 ccw(c1995.86,3030) 2020,3030 2020,3710 ccw(c1970,3710) 1970,3760 1780,3760 ccw(c1780,3710) 1730,3710 1730,3471.42 ccw(c1830,3471.42) 1759.29,3400.71 1860.71,3299.29 cw(c1790,3228.58) 1890,3228.58 1890,2945 ccw(c1905,2945) 1905,2930
PVIN_P1 on Signal Layer 5 "SIGNAL_LAYER_5_PVIN_P1_P587" (solid, remove dead copper, pour order 587): 1985,1060 ccw(c1985,1070) 1995,1070 1995,1080.86 cw(c2029.14,1080.86) 2005,1105 2005,1115 cw(c2005,1125) 1995,1125 2012.93,1142.93 ccw(c1995.86,1160) 2020,1160 2020,1840 ccw(c1970,1840) 1970,1890 1780,1890 ccw(c1780,1840) 1730,1840 1730,1601.42 ccw(c1830,1601.42) 1759.29,1530.71 1860.71,1429.29 cw(c1790,1358.58) 1890,1358.58 1890,1075 ccw(c1905,1075) 1905,1060
PVIN_P1 on Signal Layer 5 "SIGNAL_LAYER_5_PVIN_P1_P588" (solid, remove dead copper, pour order 588): 850,2000 ccw(c850,2050) 900,2050 900,2458.58 ccw(c800,2458.58) 870.71,2529.29 529.29,2870.71 ccw(c458.58,2800) 458.58,2900 150,2900 ccw(c150,2850) 100,2850 100,2050 ccw(c150,2050) 150,2000
GND_P1 on Signal Layer 1 "Signal Layer 1 GND_P1" (solid, remove dead copper, pour order 557): 0,4000 4000,4000 4000,0 0,0
GND_P1 on Signal Layer 1 "Signal Layer 1 GND_P1" (solid, remove dead copper, pour order 558): 0,4000 4000,4000 4000,0 0,0
GND_P1 on Signal Layer 6 "Signal Layer 3 GND_P1" (solid, remove dead copper, pour order 559): 0,4000 4000,4000 4000,0 0,0
VSNS_N on Signal Layer 2 "SIGNAL_LAYER_2_VSNS_N_P611" (solid, remove dead copper, pour order 611): 1472,1066 ccw(c1472,1015.3) 1436.15,1051.15 1390,1005 1373,1005 1373,1009 1393.64,1029.64 ccw(c1378.27,1045) 1400,1045 ccw(c1380,1045) 1380,1065 1375,1065 1375,1080 1490,1080 1490,1066
GND_P1 on Signal Layer 2 "SIGNAL_LAYER_2_GND_P1_P593" (solid, remove dead copper, pour order 593): 0,4000 0,0 4000,0 4000,4000
PVIN_P1 on Signal Layer 2 "SIGNAL_LAYER_2_PVIN_P1_P592" (solid, remove dead copper, pour order 592): 150,2000 370,2000 ccw(c370,2050) 420,2050 420,2860 ccw(c380,2860) 380,2900 150,2900 ccw(c150,2850) 100,2850 100,2050 ccw(c150,2050)
VOUT on Signal Layer 2 "SIGNAL_LAYER_2_VOUT_P589" (solid, remove dead copper, pour order 589): 2818.58,140 ccw(c2818.58,240) 2889.29,169.29 3810.71,1090.71 ccw(c3740,1161.42) 3840,1161.42 3840,2918.58 ccw(c3740,2918.58) 3810.71,2989.29 3019.29,3780.71 ccw(c2948.58,3710) 2948.58,3810 2540,3810 ccw(c2540,3760) 2490,3760 2490,190 ccw(c2540,190) 2540,140
GND_P1 on Signal Layer 4 "SIGNAL_LAYER_4_GND_P1_P615" (solid, remove dead copper, pour order 615): 0,4000 0,0 4000,0 4000,4000
AGND_P2 on Signal Layer 4 "SIGNAL_LAYER_4_AGND_P2_P614" (solid, remove dead copper, pour order 614): 1650,1175 1670,1175 1674.39,1170.61 ccw(c1700,1196.21) 1700,1160 1705.86,1160 ccw(c1705.86,1194.14) 1730,1170 1750,1190 1765,1175 1694.75,1104.75 ccw(c1754.5,1045) 1670,1045 1650,1045
AGND_P1 on Signal Layer 4 "SIGNAL_LAYER_4_AGND_P1_P613" (solid, remove dead copper, pour order 613): 1650,3040 1670,3040 1674.39,3035.61 ccw(c1700,3061.21) 1700,3025 1705.86,3025 ccw(c1705.86,3059.14) 1730,3035 1750,3055 1765,3040 1694.75,2969.75 ccw(c1754.5,2910) 1670,2910 1650,2910
VOUT on Signal Layer 4 "SIGNAL_LAYER_4_VOUT_P590" (solid, remove dead copper, pour order 590): 2818.58,140 ccw(c2818.58,240) 2889.29,169.29 3810.71,1090.71 ccw(c3740,1161.42) 3840,1161.42 3840,2918.58 ccw(c3740,2918.58) 3810.71,2989.29 3019.29,3780.71 ccw(c2948.58,3710) 2948.58,3810 2540,3810 ccw(c2540,3760) 2490,3760 2490,190 ccw(c2540,190) 2540,140
GND_P1 on Signal Layer 3 "SIGNAL_LAYER_3_GND_P1_P594" (solid, remove dead copper, pour order 594): 0,4000 0,0 4000,0 4000,4000
PVIN_P1 on Signal Layer 3 "SIGNAL_LAYER_3_PVIN_P1_P591" (solid, remove dead copper, pour order 591): 370,2000 ccw(c370,2050) 420,2050 420,2850 ccw(c370,2850) 370,2900 150,2900 ccw(c150,2850) 100,2850 100,2050 ccw(c150,2050) 150,2000

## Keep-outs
Keep-Out Layer:
  lines w10: -5,0 ccw(c0,0) 0,-5 ; -5,0 ccw(c0,0) 0,-5 ; -5,0 -5,4000 ; -5,4000 cw(c0,4000) 0,4005 ; -5,4000 cw(c0,4000) 0,4005 ; 0,-5 4000,-5 ; 0,4005 4000,4005 ; 4000,-5 ccw(c4000,0) 4005,0 ; 4000,-5 ccw(c4000,0) 4005,0 ; 4000,4005 cw(c4000,4000) 4005,4000 ; 4000,4005 cw(c4000,4000) 4005,4000 ; 4005,0 4005,4000
  text ".Layer_Name" at 700,-700 h60

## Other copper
Top Layer:
  pour cut-out: 1700,3930 cw(c1700,3875) 1755,3875 cw(c1700,3875) 1700,3820 cw(c1700,3875) 1645,3875 cw(c1700,3875)
  pour cut-out: 1525,3930 cw(c1525,3875) 1580,3875 cw(c1525,3875) 1525,3820 cw(c1525,3875) 1470,3875 cw(c1525,3875)
  pour cut-out: 2850,3930 cw(c2850,3875) 2905,3875 cw(c2850,3875) 2850,3820 cw(c2850,3875) 2795,3875 cw(c2850,3875)
  pour cut-out: 3025,3930 cw(c3025,3875) 3080,3875 cw(c3025,3875) 3025,3820 cw(c3025,3875) 2970,3875 cw(c3025,3875)
  pour cut-out: 3800,855 cw(c3800,800) 3855,800 cw(c3800,800) 3800,745 cw(c3800,800) 3745,800 cw(c3800,800)
  pour cut-out: 3800,630 cw(c3800,575) 3855,575 cw(c3800,575) 3800,520 cw(c3800,575) 3745,575 cw(c3800,575)
  pour cut-out: 3225,480 cw(c3225,425) 3280,425 cw(c3225,425) 3225,370 cw(c3225,425) 3170,425 cw(c3225,425)
  pour cut-out: 2900,280 cw(c2900,225) 2955,225 cw(c2900,225) 2900,170 cw(c2900,225) 2845,225 cw(c2900,225)
  pour cut-out: 3075,280 cw(c3075,225) 3130,225 cw(c3075,225) 3075,170 cw(c3075,225) 3020,225 cw(c3075,225)
  pour cut-out: 1400,1705 cw(c1400,1650) 1455,1650 cw(c1400,1650) 1400,1595 cw(c1400,1650) 1345,1650 cw(c1400,1650)
  pour cut-out: 1225,1705 cw(c1225,1650) 1280,1650 cw(c1225,1650) 1225,1595 cw(c1225,1650) 1170,1650 cw(c1225,1650)
  text ".Layer_Name" at 840,-670 h60
Signal Layer 2:
  pour cut-out: 1225,1705 cw(c1225,1650) 1280,1650 cw(c1225,1650) 1225,1595 cw(c1225,1650) 1170,1650 cw(c1225,1650)
  pour cut-out: 1400,1705 cw(c1400,1650) 1455,1650 cw(c1400,1650) 1400,1595 cw(c1400,1650) 1345,1650 cw(c1400,1650)
  pour cut-out: 1700,3930 cw(c1700,3875) 1755,3875 cw(c1700,3875) 1700,3820 cw(c1700,3875) 1645,3875 cw(c1700,3875)
  pour cut-out: 1525,3930 cw(c1525,3875) 1580,3875 cw(c1525,3875) 1525,3820 cw(c1525,3875) 1470,3875 cw(c1525,3875)
  pour cut-out: 2850,3930 cw(c2850,3875) 2905,3875 cw(c2850,3875) 2850,3820 cw(c2850,3875) 2795,3875 cw(c2850,3875)
  pour cut-out: 3025,3930 cw(c3025,3875) 3080,3875 cw(c3025,3875) 3025,3820 cw(c3025,3875) 2970,3875 cw(c3025,3875)
  pour cut-out: 3800,855 cw(c3800,800) 3855,800 cw(c3800,800) 3800,745 cw(c3800,800) 3745,800 cw(c3800,800)
  pour cut-out: 3800,630 cw(c3800,575) 3855,575 cw(c3800,575) 3800,520 cw(c3800,575) 3745,575 cw(c3800,575)
  pour cut-out: 3225,480 cw(c3225,425) 3280,425 cw(c3225,425) 3225,370 cw(c3225,425) 3170,425 cw(c3225,425)
  pour cut-out: 3075,280 cw(c3075,225) 3130,225 cw(c3075,225) 3075,170 cw(c3075,225) 3020,225 cw(c3075,225)
  pour cut-out: 2900,280 cw(c2900,225) 2955,225 cw(c2900,225) 2900,170 cw(c2900,225) 2845,225 cw(c2900,225)
  text ".Layer_Name" at 680,-670 h60
Signal Layer 4:
  pour cut-out: 3225,425 3280,425 3280,428.79 cw(c3331.21,428.79) 3295,465 3299.39,469.39 cw(c3325,443.79) 3325,480 3435.86,480 cw(c3435.86,445.86) 3460,470 3482.93,447.07 ccw(c3500,464.14) 3500,440 3850,440 3930,520 3930,1890 3852.07,1967.93 ccw(c3835,1950.86) 3835,1975 3779.14,1975 ccw(c3779.14,1940.86) 3755,1965 3755,1945 3757.93,1942.07 ccw(c3775,1959.14) 3775,1935 3810.86,1935 cw(c3810.86,1900.86) 3835,1925 3879.39,1880.61 cw(c3853.79,1855) 3890,1855 3890,554.14 cw(c3855.86,554.14) 3880,530 3840.61,490.61 cw(c3815,516.21) 3815,480 3524.14,480 cw(c3524.14,514.14) 3500,490 3477.07,512.93 ccw(c3460,495.86) 3460,520 3297.07,520 ccw(c3297.07,502.93) 3285,515 3267.68,497.68 cw(c3225,540.36) 3225,480
  pour cut-out: 3080,3875 cw(c3025,3875) 3025,3820 3020,3820 cw(c3020,3870) 2970,3870 2970,3875 cw(c3025,3875) 3025,3930 cw(c3025,3875)
  pour cut-out: 2905,3875 cw(c2850,3875) 2850,3820 2845,3820 cw(c2845,3870) 2795,3870 2795,3875 cw(c2850,3875) 2850,3930 cw(c2850,3875)
  pour cut-out: 1755,3875 cw(c1700,3875) 1700,3820 1695,3820 cw(c1695,3870) 1645,3870 1645,3875 cw(c1700,3875) 1700,3930 cw(c1700,3875)
  pour cut-out: 1580,3875 cw(c1525,3875) 1525,3820 1520,3820 cw(c1520,3870) 1470,3870 1470,3875 cw(c1525,3875) 1525,3930 cw(c1525,3875)
  pour cut-out: 1455,1650 cw(c1400,1650) 1400,1595 1395,1595 cw(c1395,1645) 1345,1645 1345,1650 cw(c1400,1650) 1400,1705 cw(c1400,1650)
  pour cut-out: 1280,1650 cw(c1225,1650) 1225,1595 1220,1595 cw(c1220,1645) 1170,1645 1170,1650 cw(c1225,1650) 1225,1705 cw(c1225,1650)
  pour cut-out: 3855,575 cw(c3800,575) 3800,520 3795,520 cw(c3795,570) 3745,570 3745,575 cw(c3800,575) 3800,630 cw(c3800,575)
  pour cut-out: 3855,800 cw(c3800,800) 3800,745 3795,745 cw(c3795,795) 3745,795 3745,800 cw(c3800,800) 3800,855 cw(c3800,800)
  pour cut-out: 3130,225 cw(c3075,225) 3075,170 3070,170 cw(c3070,220) 3020,220 3020,225 cw(c3075,225) 3075,280 cw(c3075,225)
  pour cut-out: 2955,225 cw(c2900,225) 2900,170 2895,170 cw(c2895,220) 2845,220 2845,225 cw(c2900,225) 2900,280 cw(c2900,225)
  pour cut-out: 3280,425 cw(c3225,425) 3225,370 3220,370 cw(c3220,420) 3170,420 3170,425 cw(c3225,425) 3225,480 cw(c3225,425)
  text ".Layer_Name" at 680,-670 h60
